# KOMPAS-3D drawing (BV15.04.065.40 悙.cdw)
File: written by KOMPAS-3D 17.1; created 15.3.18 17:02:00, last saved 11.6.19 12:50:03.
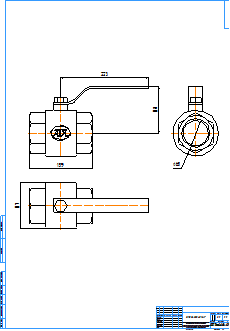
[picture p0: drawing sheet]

Sheet 1: A1, portrait

Title block, sheet 1: name: BV15.04.065.40 Р/Р; material: Внимание! Данный продукт является объектом авторского права ООО «Торговый Дом АДЛ». / Запрещается изменение, копирование, распространение / (в том числе путем копирования на другие сайты и ресурсы в Интернете) / или любое иное использование информации и объектов без предварительного / согласия правообладателя (ООО «Торговый Дом АДЛ»).; mass: 5,1; sheets: 1; organisation: ООО "Торговый дом АДЛ"; sheet format: A1; stored path: \\adlc.lan\data\АДЛ_ПКД\3D-модели\ADL production\Краны шаровые серии BV\BV15\KOMPAS 2D\BV15.04.065.40 РР.cdw

Views: Вид 1, Проекционный вид 2, Проекционный вид 3
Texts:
  kka
  adl
Dimensions and other numbers on the sheet: 159; 223; 118; 65; 117; 1:1; 1; 5,1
